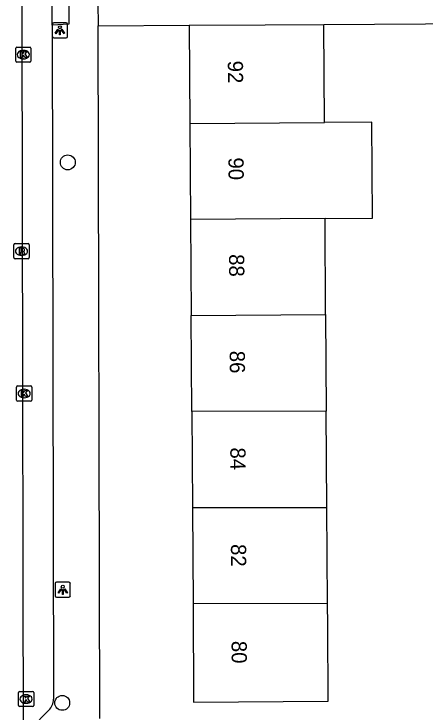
# Model space of a CAD drawing. Extents: x 160732 to 162105, y 387428 to 388479.
# Drawn here: x 161160.26 to 161187.3, y 388253.41 to 388299.29 of the extents above; entities that cross this region are included whole.
import ezdxf

# ---------------------------------------------------------------- set-up
doc = ezdxf.new("R2010")
doc.units = 0
for name, color, linetype in [('IMGEO_Boom', 7, 'Continuous'), ('IMGEO_Kolk', 7, 'Continuous'), ('IMGEO_Lichtpunt', 7, 'Continuous'), ('IMGEO_Pand', 7, 'Continuous'), ('IMGEO_Pand_nummerreeks', 7, 'Continuous'), ('IMGEO_Rijbaan_lokaal_open', 7, 'Continuous'), ('IMGEO_Rioolput', 7, 'Continuous'), ('IMGEO_Voetpad_open', 7, 'Continuous')]:
    doc.layers.add(name, color=color, linetype=linetype)

msp = doc.modelspace()

# ---------------------------------------------------------------- linework, layer by layer
at = {"layer": 'IMGEO_Boom'}
for centre in [(161163.801, 388289.534), (161163.431, 388254.01)]:
    msp.add_circle(centre, 0.489, dxfattribs=at)
at = {"layer": 'IMGEO_Kolk'}
for p, q in [((161160.447, 388297.118), (161161.299, 388297.118)), ((161160.372, 388296.192), (161160.372, 388297.044)), ((161160.86, 388296.898), (161160.885, 388296.898)), ((161161.373, 388297.044), (161161.373, 388296.192)), ((161160.883, 388296.338), (161160.858, 388296.338)), ((161161.299, 388296.118), (161160.447, 388296.118)), ((161160.429, 388273.916), (161160.429, 388274.768)), ((161160.504, 388274.842), (161161.356, 388274.842)), ((161161.43, 388274.768), (161161.43, 388273.916)), ((161160.917, 388274.622), (161160.942, 388274.622)), ((161161.356, 388273.842), (161160.504, 388273.842)), ((161160.94, 388274.062), (161160.915, 388274.062)), ((161160.554, 388253.835), (161160.554, 388254.687)), ((161160.629, 388254.761), (161161.481, 388254.761)), ((161161.042, 388254.541), (161161.067, 388254.541)), ((161161.555, 388254.687), (161161.555, 388253.835)), ((161161.481, 388253.761), (161160.629, 388253.761)), ((161161.065, 388253.981), (161161.04, 388253.981))]:
    msp.add_line(p, q, dxfattribs=at)
for points in [[(161160.447, 388297.118), (161161.299, 388297.118)], [(161160.372, 388296.192), (161160.372, 388297.044)], [(161160.693, 388296.818), (161160.816, 388296.818), (161160.816, 388296.667), (161160.946, 388296.818), (161161.11, 388296.818), (161160.964, 388296.667), (161161.117, 388296.418), (161160.965, 388296.418), (161160.88, 388296.582), (161160.816, 388296.515), (161160.816, 388296.418), (161160.693, 388296.418), (161160.693, 388296.818)], [(161161.373, 388297.044), (161161.373, 388296.192)], [(161161.299, 388296.118), (161160.447, 388296.118)], [(161160.429, 388273.916), (161160.429, 388274.768)], [(161160.504, 388274.842), (161161.356, 388274.842)], [(161161.43, 388274.768), (161161.43, 388273.916)], [(161160.75, 388274.542), (161160.873, 388274.542), (161160.873, 388274.391), (161161.003, 388274.542), (161161.167, 388274.542), (161161.021, 388274.391), (161161.174, 388274.142), (161161.022, 388274.142), (161160.937, 388274.306), (161160.873, 388274.239), (161160.873, 388274.142), (161160.75, 388274.142), (161160.75, 388274.542)], [(161161.356, 388273.842), (161160.504, 388273.842)], [(161160.554, 388253.835), (161160.554, 388254.687)], [(161160.629, 388254.761), (161161.481, 388254.761)], [(161160.875, 388254.461), (161160.998, 388254.461), (161160.998, 388254.31), (161161.128, 388254.461), (161161.292, 388254.461), (161161.146, 388254.31), (161161.299, 388254.061), (161161.147, 388254.061), (161161.062, 388254.225), (161160.998, 388254.158), (161160.998, 388254.061), (161160.875, 388254.061), (161160.875, 388254.461)], [(161161.555, 388254.687), (161161.555, 388253.835)], [(161161.481, 388253.761), (161160.629, 388253.761)]]:
    msp.add_lwpolyline(points, dxfattribs=at)
for centre, start, end in [((161160.449, 388297.042), 91.552, 178.448), ((161160.449, 388297.042), 91.552, 178.448), ((161161.297, 388297.042), 1.552, 88.448), ((161161.297, 388297.042), 1.552, 88.448), ((161160.449, 388296.194), 181.552, 268.448), ((161160.449, 388296.194), 181.552, 268.448), ((161161.297, 388296.194), 271.552, 358.448), ((161161.297, 388296.194), 271.552, 358.448), ((161160.506, 388274.766), 91.552, 178.448), ((161160.506, 388274.766), 91.552, 178.448), ((161161.354, 388274.766), 1.552, 88.448), ((161161.354, 388274.766), 1.552, 88.448), ((161160.506, 388273.918), 181.552, 268.448), ((161160.506, 388273.918), 181.552, 268.448), ((161161.354, 388273.918), 271.552, 358.448), ((161161.354, 388273.918), 271.552, 358.448), ((161160.631, 388254.685), 91.552, 178.448), ((161160.631, 388254.685), 91.552, 178.448), ((161161.479, 388254.685), 1.552, 88.448), ((161161.479, 388254.685), 1.552, 88.448), ((161160.631, 388253.837), 181.552, 268.448), ((161160.631, 388253.837), 181.552, 268.448), ((161161.479, 388253.837), 271.552, 358.448), ((161161.479, 388253.837), 271.552, 358.448)]:
    msp.add_arc(centre, 0.0765, start, end, dxfattribs=at)
for centre, major_axis, ratio, start_param, end_param in [((161160.859, 388296.618), (-0.387, 0.002), 0.722429, 4.712389, 7.853982), ((161160.884, 388296.618), (-0.39, 0.002), 0.717154, 1.570796, 4.712389), ((161160.916, 388274.342), (-0.387, 0.002), 0.722429, 4.712389, 7.853982), ((161160.941, 388274.342), (-0.39, 0.002), 0.717154, 1.570796, 4.712389), ((161161.041, 388254.261), (-0.387, 0.002), 0.722429, 4.712389, 7.853982), ((161161.066, 388254.261), (-0.39, 0.002), 0.717154, 1.570796, 4.712389)]:
    msp.add_ellipse(centre, major_axis=major_axis, ratio=ratio, start_param=start_param, end_param=end_param, dxfattribs=at)
at = {"layer": 'IMGEO_Lichtpunt'}
for p, q in [((161162.78, 388298.619), (161162.78, 388297.812)), ((161162.78, 388298.619), (161162.78, 388297.812)), ((161163.682, 388298.714), (161162.874, 388298.714)), ((161163.682, 388298.714), (161162.874, 388298.714)), ((161163.776, 388297.812), (161163.776, 388298.619)), ((161163.776, 388297.812), (161163.776, 388298.619)), ((161162.874, 388297.718), (161163.682, 388297.718)), ((161162.874, 388297.718), (161163.682, 388297.718)), ((161162.97, 388261.849), (161162.97, 388261.042)), ((161162.97, 388261.849), (161162.97, 388261.042)), ((161163.872, 388261.944), (161163.064, 388261.944)), ((161163.872, 388261.944), (161163.064, 388261.944)), ((161163.966, 388261.042), (161163.966, 388261.849)), ((161163.966, 388261.042), (161163.966, 388261.849)), ((161163.064, 388260.948), (161163.872, 388260.948)), ((161163.064, 388260.948), (161163.872, 388260.948))]:
    msp.add_line(p, q, dxfattribs=at)
for points in [[(161163.154, 388298.283), (161163.193, 388298.255), (161163.005, 388297.993), (161162.967, 388298.02), (161163.154, 388298.283)], [(161163.256, 388298.235), (161163.303, 388298.235), (161163.303, 388297.913), (161163.256, 388297.913), (161163.256, 388298.235)], [(161163.366, 388298.255), (161163.404, 388298.282), (161163.591, 388298.02), (161163.552, 388297.992), (161163.366, 388298.255)], [(161163.344, 388261.513), (161163.383, 388261.485), (161163.195, 388261.223), (161163.157, 388261.25), (161163.344, 388261.513)], [(161163.446, 388261.465), (161163.493, 388261.465), (161163.493, 388261.143), (161163.446, 388261.143), (161163.446, 388261.465)], [(161163.556, 388261.485), (161163.594, 388261.512), (161163.781, 388261.25), (161163.742, 388261.222), (161163.556, 388261.485)]]:
    msp.add_lwpolyline(points, dxfattribs=at)
for centre in [(161163.279, 388298.417), (161163.469, 388261.647)]:
    msp.add_circle(centre, 0.0994, dxfattribs=at)
for centre, start, end in [((161162.874, 388298.619), 90, 180), ((161162.874, 388298.619), 90, 180), ((161163.682, 388298.619), 0, 90), ((161163.682, 388298.619), 0, 90), ((161162.874, 388297.812), 180, 270), ((161162.874, 388297.812), 180, 270), ((161163.682, 388297.812), 270, 0), ((161163.682, 388297.812), 270, 360), ((161163.064, 388261.849), 90, 180), ((161163.064, 388261.849), 90, 180), ((161163.872, 388261.849), 0, 90), ((161163.872, 388261.849), 0, 90), ((161163.064, 388261.042), 180, 270), ((161163.064, 388261.042), 180, 270), ((161163.872, 388261.042), 270, 0), ((161163.872, 388261.042), 270, 360)]:
    msp.add_arc(centre, 0.0946, start, end, dxfattribs=at)
at = {"layer": 'IMGEO_Pand'}
for points in [[(161171.786, 388298.548), (161176.786, 388298.581), (161180.636, 388298.606)], [(161171.786, 388298.548), (161171.828, 388292.09)], [(161180.678, 388292.149), (161180.636, 388298.606)], [(161171.828, 388292.09), (161180.678, 388292.149)], [(161171.828, 388292.09), (161171.87, 388285.78)], [(161180.719, 388285.839), (161183.836, 388285.86), (161183.795, 388292.17), (161180.678, 388292.149)], [(161180.719, 388285.839), (161171.87, 388285.78)], [(161171.87, 388285.78), (161171.911, 388279.47)], [(161180.761, 388279.529), (161180.719, 388285.839)], [(161171.911, 388279.47), (161180.761, 388279.529)], [(161171.953, 388273.161), (161171.911, 388279.47)], [(161180.761, 388279.529), (161180.802, 388273.182)], [(161180.802, 388273.182), (161171.953, 388273.161)], [(161171.953, 388273.161), (161171.994, 388266.841)], [(161180.843, 388266.86), (161180.802, 388273.182)], [(161171.994, 388266.841), (161180.843, 388266.86)], [(161171.994, 388266.841), (161172.036, 388260.511)], [(161180.885, 388260.541), (161180.843, 388266.86)], [(161180.885, 388260.541), (161172.036, 388260.511)], [(161172.036, 388260.511), (161172.078, 388254.067), (161180.927, 388254.125), (161180.894, 388259.125), (161180.885, 388260.541)]]:
    msp.add_lwpolyline(points, dxfattribs=at)
at = {"layer": 'IMGEO_Rijbaan_lokaal_open'}
msp.add_lwpolyline([(161160.722, 388322.777), (161160.858, 388251.078)], dxfattribs=at)
at = {"layer": 'IMGEO_Rioolput'}
for p, q in [((161160.257, 388283.272), (161160.257, 388284.124)), ((161160.332, 388284.198), (161161.184, 388284.198)), ((161160.745, 388283.978), (161160.77, 388283.978)), ((161161.258, 388284.124), (161161.258, 388283.272)), ((161160.768, 388283.418), (161160.743, 388283.418)), ((161161.184, 388283.198), (161160.332, 388283.198))]:
    msp.add_line(p, q, dxfattribs=at)
for points in [[(161160.257, 388283.272), (161160.257, 388284.124)], [(161160.332, 388284.198), (161161.184, 388284.198)], [(161160.846, 388283.896), (161160.594, 388283.898), (161160.594, 388283.498)], [(161160.772, 388283.817), (161160.718, 388283.817), (161160.718, 388283.736)], [(161161.258, 388284.124), (161161.258, 388283.272)], [(161160.594, 388283.498), (161160.718, 388283.498), (161160.718, 388283.66), (161160.729, 388283.66)], [(161160.718, 388283.736), (161160.77, 388283.736)], [(161160.776, 388283.631), (161160.847, 388283.498), (161160.987, 388283.498), (161160.922, 388283.624)], [(161161.184, 388283.198), (161160.332, 388283.198)]]:
    msp.add_lwpolyline(points, dxfattribs=at)
for centre, radius, start, end in [((161160.334, 388284.122), 0.0765, 91.552, 178.448), ((161160.334, 388284.122), 0.0765, 91.552, 178.448), ((161160.778, 388283.721), 0.0964, 77.0061, 93.1865), ((161160.792, 388283.778), 0.0378, 276.6634, 79.6772), ((161160.845, 388283.786), 0.109, 350.3612, 89.416), ((161161.182, 388284.122), 0.0765, 1.552, 88.448), ((161161.182, 388284.122), 0.0765, 1.552, 88.448), ((161160.728, 388283.607), 0.0533, 26.0293, 88.6989), ((161160.754, 388283.925), 0.19, 274.7715, 282.9687), ((161160.843, 388283.786), 0.112, 277.5842, 350.9817), ((161160.827, 388283.571), 0.108, 29.5134, 73.7905), ((161160.334, 388283.274), 0.0765, 181.552, 268.448), ((161160.334, 388283.274), 0.0765, 181.552, 268.448), ((161161.182, 388283.274), 0.0765, 271.552, 358.448), ((161161.182, 388283.274), 0.0765, 271.552, 358.448)]:
    msp.add_arc(centre, radius, start, end, dxfattribs=at)
for centre, major_axis, ratio, start_param, end_param in [((161160.744, 388283.698), (-0.387, 0.002), 0.722429, 4.712389, 7.853982), ((161160.769, 388283.698), (-0.39, 0.002), 0.717154, 1.570796, 4.712389)]:
    msp.add_ellipse(centre, major_axis=major_axis, ratio=ratio, start_param=start_param, end_param=end_param, dxfattribs=at)
at = {"layer": 'IMGEO_Voetpad_open'}
for points in [[(161162.765, 388298.562), (161162.729, 388304.495)], [(161162.729, 388304.495), (161163.831, 388304.455), (161163.859, 388298.611), (161162.765, 388298.562)], [(161165.786, 388300.045), (161165.791, 388298.515)], [(161162.765, 388298.562), (161162.868, 388254.251)], [(161165.791, 388298.515), (161171.786, 388298.548)], [(161165.912, 388252.974), (161165.791, 388298.515)], [(161180.636, 388298.606), (161190.665, 388298.673), (161190.663, 388297.215)], [(161162.557, 388253.528), (161161.389, 388252.341)]]:
    msp.add_lwpolyline(points, dxfattribs=at)
msp.add_arc((161161.781, 388254.29), 1.088, 315.5201, 357.9298, dxfattribs=at)

# ---------------------------------------------------------------- texts
at = {"layer": 'IMGEO_Pand_nummerreeks'}
for s, rotation, p in [('92', 270.3761, (161174.322, 388296.216)), ('90', 270.3779, (161174.364, 388289.855)), ('88', 270.3761, (161174.405, 388283.501)), ('86', 270.3761, (161174.447, 388277.15)), ('84', 270.3761, (161174.489, 388270.795)), ('82', 270.3761, (161174.53, 388264.444)), ('80', 270.3761, (161174.572, 388258.083))]:
    msp.add_text(s, height=1, rotation=rotation, dxfattribs=at).set_placement(p)

doc.saveas('drawing.dxf')
